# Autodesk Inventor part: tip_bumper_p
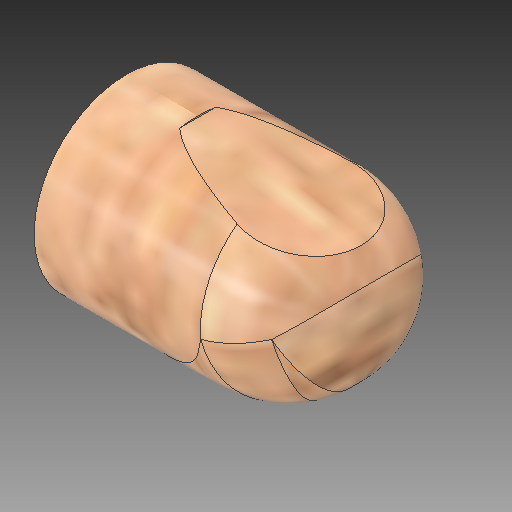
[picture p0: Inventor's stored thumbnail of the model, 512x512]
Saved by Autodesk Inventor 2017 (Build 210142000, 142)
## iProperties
Created: 2017-05
Part Number: tip_bumper_p
Material: Generic
Document SubType Name: Modeling
Designer: alez_
Density: 1 g/cm^3
Appearance: Default
Author: alez_
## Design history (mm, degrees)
derived "Tip_bumper.ipt" dims "d0" = 9
feature "Solid1::Tip_bumper.ipt" dims "d0" = 9
tag "TaggingFeature1"
body "Solid1"
